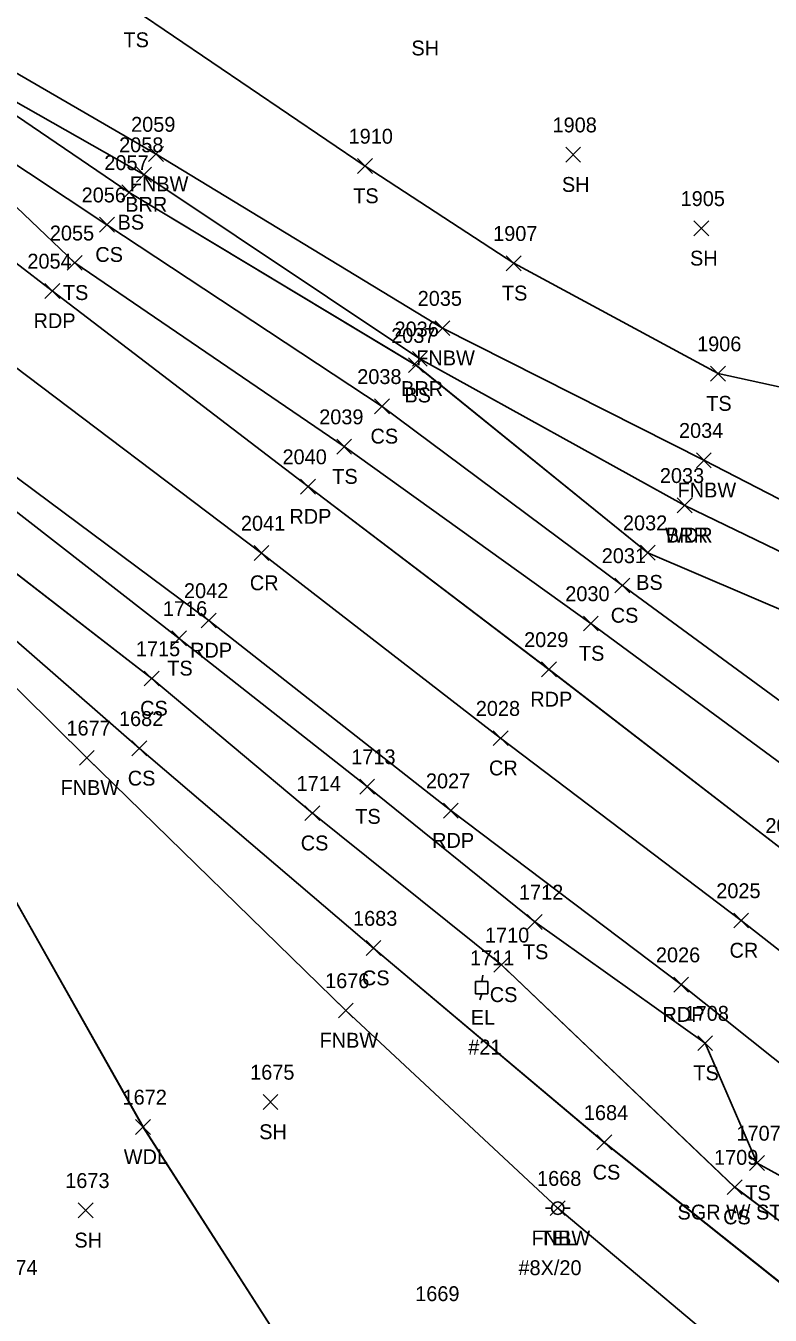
# Model space of a CAD drawing. Extents: x 1415642 to 1422021, y 544543 to 547232.
# Drawn here: x 1415866.3 to 1415966.4, y 546920.1 to 547093.4 of the extents above; entities that cross this region are included whole.
import ezdxf

# ---------------------------------------------------------------- set-up
doc = ezdxf.new("R2010")
doc.units = 0
for name, color, linetype in [('L_A', 7, 'Continuous'), ('L_C', 7, 'Continuous'), ('L_I', 7, 'Continuous'), ('L_TIC', 7, 'Continuous'), ('LABL', 7, 'Continuous'), ('LAWA', 7, 'Continuous'), ('LELB', 7, 'Continuous'), ('LFNC', 7, 'Continuous'), ('P_A', 7, 'Continuous'), ('P_I', 7, 'Continuous'), ('P_TIC', 7, 'Continuous'), ('PET', 7, 'Continuous'), ('PRC', 7, 'Continuous'), ('R_C', 7, 'Continuous'), ('U_A', 7, 'Continuous'), ('U_C', 7, 'Continuous'), ('U_I', 7, 'Continuous'), ('UEPT', 7, 'Continuous'), ('UP', 7, 'Continuous')]:
    doc.layers.add(name, color=color, linetype=linetype)

msp = doc.modelspace()

# ---------------------------------------------------------------- linework, layer by layer
at = {"layer": 'L_TIC'}
for points in [[(1415882.85, 547075.17), (1415884.85, 547077.17)], [(1415884.85, 547075.17), (1415882.85, 547077.17)], [(1415938.9, 547075.09), (1415940.9, 547077.09)], [(1415940.9, 547075.09), (1415938.9, 547077.09)], [(1415881.22, 547072.42), (1415883.22, 547074.42)], [(1415883.22, 547072.42), (1415881.22, 547074.42)], [(1415910.93, 547073.57), (1415912.93, 547075.57)], [(1415912.93, 547073.57), (1415910.93, 547075.57)], [(1415879.24, 547070.02), (1415881.24, 547072.02)], [(1415881.24, 547070.02), (1415879.24, 547072.02)], [(1415876.25, 547065.68), (1415878.25, 547067.68)], [(1415878.25, 547065.68), (1415876.25, 547067.68)], [(1415956.1, 547065.19), (1415958.1, 547067.19)], [(1415958.1, 547065.19), (1415956.1, 547067.19)], [(1415871.92, 547060.56), (1415873.92, 547062.56)], [(1415873.92, 547060.56), (1415871.92, 547062.56)], [(1415930.91, 547060.5), (1415932.91, 547062.5)], [(1415932.91, 547060.5), (1415930.91, 547062.5)], [(1415921.34, 547051.78), (1415923.34, 547053.78)], [(1415923.34, 547051.78), (1415921.34, 547053.78)], [(1415917.77, 547046.8), (1415919.77, 547048.8)], [(1415919.77, 547046.8), (1415917.77, 547048.8)], [(1415918.29, 547047.66), (1415920.29, 547049.66)], [(1415920.29, 547047.66), (1415918.29, 547049.66)], [(1415958.36, 547045.67), (1415960.36, 547047.67)], [(1415960.36, 547045.67), (1415958.36, 547047.67)], [(1415913.22, 547041.27), (1415915.22, 547043.27)], [(1415915.22, 547041.27), (1415913.22, 547043.27)], [(1415908.12, 547035.86), (1415910.12, 547037.86)], [(1415910.12, 547035.86), (1415908.12, 547037.86)], [(1415956.45, 547034.03), (1415958.45, 547036.03)], [(1415958.45, 547034.03), (1415956.45, 547036.03)], [(1415953.88, 547027.97), (1415955.88, 547029.97)], [(1415955.88, 547027.97), (1415953.88, 547029.97)], [(1415953.88, 547027.97), (1415955.88, 547029.97)], [(1415955.88, 547027.97), (1415953.88, 547029.97)], [(1415948.92, 547021.61), (1415950.92, 547023.61)], [(1415950.92, 547021.61), (1415948.92, 547023.61)], [(1415945.5, 547017.2), (1415947.5, 547019.2)], [(1415947.5, 547017.2), (1415945.5, 547019.2)], [(1415941.26, 547012.09), (1415943.26, 547014.09)], [(1415943.26, 547012.09), (1415941.26, 547014.09)], [(1415885.95, 547010.09), (1415887.95, 547012.09)], [(1415887.95, 547010.09), (1415885.95, 547012.09)], [(1415882.27, 547004.7), (1415884.27, 547006.7)], [(1415884.27, 547004.7), (1415882.27, 547006.7)], [(1415880.61, 546995.31), (1415882.61, 546997.31)], [(1415882.61, 546995.31), (1415880.61, 546997.31)], [(1415880.61, 546995.31), (1415882.61, 546997.31)], [(1415882.61, 546995.31), (1415880.61, 546997.31)], [(1415873.55, 546994.04), (1415875.55, 546996.04)], [(1415875.55, 546994.04), (1415873.55, 546996.04)], [(1415911.21, 546990.17), (1415913.21, 546992.17)], [(1415913.21, 546990.17), (1415911.21, 546992.17)], [(1415903.85, 546986.6), (1415905.85, 546988.6)], [(1415905.85, 546986.6), (1415903.85, 546988.6)], [(1415933.73, 546971.98), (1415935.73, 546973.98)], [(1415935.73, 546971.98), (1415933.73, 546973.98)], [(1415912.06, 546968.47), (1415914.06, 546970.47)], [(1415914.06, 546968.47), (1415912.06, 546970.47)], [(1415929.25, 546966.22), (1415931.25, 546968.22)], [(1415931.25, 546966.22), (1415929.25, 546968.22)], [(1415908.35, 546960.09), (1415910.35, 546962.09)], [(1415910.35, 546960.09), (1415908.35, 546962.09)], [(1415956.63, 546955.7), (1415958.63, 546957.7)], [(1415958.63, 546955.7), (1415956.63, 546957.7)], [(1415898.23, 546947.79), (1415900.23, 546949.79)], [(1415900.23, 546947.79), (1415898.23, 546949.79)], [(1415881.09, 546944.44), (1415883.09, 546946.44)], [(1415883.09, 546944.44), (1415881.09, 546946.44)], [(1415943.07, 546942.36), (1415945.07, 546944.36)], [(1415945.07, 546942.36), (1415943.07, 546944.36)], [(1415963.6, 546939.59), (1415965.6, 546941.59)], [(1415965.6, 546939.59), (1415963.6, 546941.59)], [(1415960.59, 546936.35), (1415962.59, 546938.35)], [(1415962.59, 546936.35), (1415960.59, 546938.35)], [(1415873.39, 546933.23), (1415875.39, 546935.23)], [(1415875.39, 546933.23), (1415873.39, 546935.23)], [(1415936.82, 546933.52), (1415938.82, 546935.52)], [(1415938.82, 546933.52), (1415936.82, 546935.52)]]:
    msp.add_lwpolyline(points, dxfattribs=at)
at = {"layer": 'LABL'}
for points in [[(1415954.88, 547028.96), (1415919.29, 547048.67), (1415882.22, 547073.43), (1415848.8, 547092.4), (1415822.78, 547108.48), (1415823.18, 547113.64)], [(1415954.88, 547028.97), (1415919.29, 547048.66), (1415882.22, 547073.42), (1415848.8, 547092.4), (1415822.78, 547108.48), (1415823.18, 547113.63)]]:
    msp.add_lwpolyline(points, dxfattribs=at)
at = {"layer": 'LAWA'}
for points in [[(1415914.11, 546834.35), (1415931.31, 546850.74), (1415944.85, 546869.92), (1415908.68, 546903.98), (1415882.09, 546945.44), (1415862.73, 546979.72), (1415851.29, 546999.16), (1415831.18, 547012.42), (1415802.21, 547036.19), (1415763.17, 547054.94), (1415718.14, 547089.46), (1415689.93, 547108.01)], [(1415914.12, 546834.35), (1415931.31, 546850.75), (1415944.86, 546869.92), (1415908.68, 546903.98), (1415882.1, 546945.44), (1415862.73, 546979.72), (1415851.29, 546999.15), (1415831.18, 547012.42), (1415802.2, 547036.19), (1415763.17, 547054.94), (1415718.15, 547089.45), (1415689.93, 547108.01)], [(1416240.56, 546960.73), (1416233.2, 546953.27), (1416224.51, 546941.93), (1416214.85, 546929.39), (1416199.95, 546923.14), (1416193.46, 546920.24), (1416179.13, 546920.7), (1416159.93, 546927.15), (1416126.32, 546945.38), (1416100.02, 546952.8), (1416028.43, 546991.66), (1415993.05, 547010.51), (1415954.88, 547028.97)], [(1416240.56, 546960.73), (1416233.2, 546953.27), (1416224.51, 546941.93), (1416214.86, 546929.39), (1416199.95, 546923.14), (1416193.46, 546920.24), (1416179.13, 546920.7), (1416159.93, 546927.15), (1416126.32, 546945.39), (1416100.02, 546952.81), (1416028.43, 546991.66), (1415993.05, 547010.51), (1415954.88, 547028.96)]]:
    msp.add_lwpolyline(points, dxfattribs=at)
at = {"layer": 'LELB'}
for points in [[(1416091.47, 546896.23), (1416067.28, 546915.33), (1416036.7, 546941.48), (1416008.25, 546963.65), (1415975.6, 546988.56), (1415942.26, 547013.09), (1415909.12, 547036.86), (1415872.92, 547061.56), (1415845.5, 547087.74), (1415809.03, 547112.5), (1415805.73, 547114.89), (1415787.7, 547125.97), (1415788.24, 547129.84), (1415790.68, 547131.85)], [(1416091.47, 546896.23), (1416067.28, 546915.33), (1416036.71, 546941.48), (1416008.26, 546963.65), (1415975.6, 546988.56), (1415942.26, 547013.09), (1415909.12, 547036.86), (1415872.92, 547061.56), (1415845.5, 547087.74), (1415809.04, 547112.5), (1415805.73, 547114.9), (1415787.7, 547125.97), (1415788.24, 547129.84), (1415790.68, 547131.85)], [(1416157.94, 546955.38), (1416155.92, 546957.27), (1416135.55, 546960.79), (1416132.49, 546973.78), (1416110.9, 546979.13), (1416081.52, 546992.2), (1416051.18, 547012.47), (1416023.77, 547025.27), (1415981.89, 547041.76), (1415959.36, 547046.67), (1415931.91, 547061.5), (1415911.94, 547074.57), (1415881.06, 547095.53), (1415867.9, 547121.94)], [(1416157.94, 546955.38), (1416155.92, 546957.27), (1416135.55, 546960.79), (1416132.49, 546973.77), (1416110.9, 546979.12), (1416081.52, 546992.2), (1416051.18, 547012.47), (1416023.76, 547025.27), (1415981.89, 547041.76), (1415959.36, 547046.67), (1415931.91, 547061.5), (1415911.93, 547074.57), (1415881.06, 547095.53), (1415867.9, 547121.93)], [(1415979.27, 546932.57), (1415964.6, 546940.59), (1415957.63, 546956.7), (1415934.73, 546972.98), (1415912.21, 546991.17), (1415886.95, 547011.09), (1415854.08, 547036.67), (1415824.18, 547059.44), (1415786.82, 547087.62), (1415741.01, 547120.53)], [(1415979.28, 546932.57), (1415964.61, 546940.59), (1415957.63, 546956.7), (1415934.74, 546972.98), (1415912.22, 546991.17), (1415886.96, 547011.09), (1415854.08, 547036.67), (1415824.19, 547059.44), (1415786.82, 547087.62), (1415741.01, 547120.53)], [(1416166.26, 546865.71), (1416159.51, 546874.18), (1416128.86, 546893.05), (1416099.94, 546911.95), (1416080.11, 546927.17), (1416051.61, 546951.27), (1416024.79, 546978.54), (1415989.85, 547005.5), (1415949.92, 547022.61), (1415918.77, 547047.8), (1415880.24, 547071.02), (1415848.8, 547092.4)], [(1416166.26, 546865.71), (1416159.51, 546874.18), (1416128.86, 546893.05), (1416099.95, 546911.94), (1416080.11, 546927.17), (1416051.61, 546951.27), (1416024.79, 546978.54), (1415989.85, 547005.5), (1415949.92, 547022.61), (1415918.78, 547047.8), (1415880.25, 547071.01), (1415848.8, 547092.4)], [(1416210.45, 546810.14), (1416187.24, 546828.5), (1416172.35, 546839.03), (1416162.91, 546845.64), (1416145.69, 546861.76), (1416125.16, 546875.54), (1416093.4, 546901.43), (1416075.19, 546919.9), (1416045.66, 546942.32), (1416039.77, 546946.29), (1416015.88, 546971.97), (1415979.91, 546993.7), (1415946.5, 547018.2), (1415914.22, 547042.27), (1415877.25, 547066.68), (1415845.5, 547087.74)], [(1416210.45, 546810.14), (1416187.24, 546828.5), (1416172.36, 546839.03), (1416162.91, 546845.64), (1416145.7, 546861.76), (1416125.16, 546875.54), (1416093.4, 546901.44), (1416075.18, 546919.9), (1416045.66, 546942.32), (1416039.77, 546946.29), (1416015.88, 546971.97), (1415979.91, 546993.7), (1415946.51, 547018.2), (1415914.22, 547042.27), (1415877.24, 547066.68), (1415845.5, 547087.74)], [(1416200.69, 546756.25), (1416177.76, 546767.63), (1416166.72, 546775.57), (1416158.94, 546780.74), (1416149.8, 546790.95), (1416145.27, 546792.19), (1416135.47, 546803.24), (1416119.09, 546819.38), (1416087.86, 546845.73), (1416058.66, 546867.92), (1416017.63, 546898.15), (1415975.94, 546926.54), (1415961.59, 546937.35), (1415930.25, 546967.22), (1415904.85, 546987.6), (1415883.27, 547005.7), (1415850.56, 547030.99), (1415821.69, 547055.02)], [(1416200.69, 546756.25), (1416177.77, 546767.63), (1416166.72, 546775.57), (1416158.93, 546780.74), (1416149.8, 546790.95), (1416145.28, 546792.19), (1416135.47, 546803.24), (1416119.09, 546819.38), (1416087.87, 546845.73), (1416058.67, 546867.92), (1416017.63, 546898.16), (1415975.95, 546926.55), (1415961.6, 546937.34), (1415930.25, 546967.22), (1415904.86, 546987.6), (1415883.28, 547005.7), (1415850.57, 547030.99), (1415821.7, 547055.02)], [(1415881.61, 546996.31), (1415848.06, 547025.54), (1415815.91, 547049.29)], [(1415881.62, 546996.31), (1415848.06, 547025.54), (1415815.91, 547049.29)], [(1415881.61, 546996.31), (1415913.06, 546969.47), (1415944.07, 546943.36), (1415978.11, 546916.22), (1416009.92, 546888.85), (1416034.36, 546866.02), (1416055.92, 546848.02), (1416074.4, 546832.78), (1416094.73, 546817.39), (1416113.97, 546812.22), (1416083.13, 546840.22), (1416056.24, 546861.43), (1416014.25, 546894.44), (1415975.94, 546926.54)], [(1415881.62, 546996.31), (1415913.07, 546969.47), (1415944.08, 546943.36), (1415978.12, 546916.23), (1416009.93, 546888.84), (1416034.36, 546866.03), (1416055.93, 546848.02), (1416074.4, 546832.78), (1416094.74, 546817.39), (1416113.98, 546812.22), (1416083.14, 546840.22), (1416056.24, 546861.43), (1416014.25, 546894.43), (1415975.95, 546926.55)]]:
    msp.add_lwpolyline(points, dxfattribs=at)
at = {"layer": 'LFNC'}
for points in [[(1416067.58, 546984.06), (1416031.2, 546999.34), (1415996.11, 547015.1), (1415957.45, 547035.03), (1415922.34, 547052.78), (1415883.85, 547076.17), (1415852.09, 547094.57), (1415823.18, 547113.63), (1415819.4, 547116.14), (1415815.46, 547118.48), (1415790.83, 547135.32)], [(1416067.58, 546984.06), (1416031.2, 546999.34), (1415996.12, 547015.09), (1415957.45, 547035.03), (1415922.34, 547052.78), (1415883.85, 547076.17), (1415852.09, 547094.57), (1415823.18, 547113.64), (1415819.41, 547116.14), (1415815.45, 547118.48), (1415790.83, 547135.32)], [(1415844.05, 547025.19), (1415874.55, 546995.04)], [(1415844.05, 547025.19), (1415874.56, 546995.04)], [(1416115.75, 546796.75), (1416105.56, 546801.9), (1416090.13, 546811.78), (1416082.81, 546817.76), (1416078.29, 546817.48), (1416069.09, 546824.45), (1416051.15, 546839.14), (1416026.27, 546859.13), (1416002.28, 546878.71), (1415967.43, 546909.62), (1415937.82, 546934.52), (1415909.35, 546961.09), (1415874.55, 546995.04)], [(1416115.75, 546796.75), (1416105.57, 546801.9), (1416090.14, 546811.78), (1416082.82, 546817.76), (1416078.29, 546817.48), (1416069.1, 546824.45), (1416051.16, 546839.14), (1416026.28, 546859.13), (1416002.28, 546878.71), (1415967.43, 546909.62), (1415937.83, 546934.51), (1415909.36, 546961.09), (1415874.56, 546995.04)]]:
    msp.add_lwpolyline(points, dxfattribs=at)
at = {"layer": 'P_TIC'}
for points in [[(1415868.9, 547056.78), (1415870.9, 547058.78)], [(1415870.9, 547056.78), (1415868.9, 547058.78)], [(1415903.27, 547030.49), (1415905.27, 547032.49)], [(1415905.27, 547030.49), (1415903.27, 547032.49)], [(1415897.02, 547021.56), (1415899.02, 547023.56)], [(1415899.02, 547021.56), (1415897.02, 547023.56)], [(1415889.93, 547012.5), (1415891.93, 547014.5)], [(1415891.93, 547012.5), (1415889.93, 547014.5)], [(1415935.64, 547005.92), (1415937.64, 547007.92)], [(1415937.64, 547005.92), (1415935.64, 547007.92)], [(1415929.15, 546996.68), (1415931.15, 546998.68)], [(1415931.15, 546996.68), (1415929.15, 546998.68)], [(1415922.45, 546986.94), (1415924.45, 546988.94)], [(1415924.45, 546986.94), (1415922.45, 546988.94)], [(1415961.46, 546972.18), (1415963.46, 546974.18)], [(1415963.46, 546972.18), (1415961.46, 546974.18)], [(1415953.4, 546963.56), (1415955.4, 546965.56)], [(1415955.4, 546963.56), (1415953.4, 546965.56)]]:
    msp.add_lwpolyline(points, dxfattribs=at)
at = {"layer": 'PET'}
for points in [[(1415969.06, 546981.93), (1415936.64, 547006.92), (1415904.27, 547031.49), (1415869.9, 547057.78), (1415840.56, 547080.38), (1415803.16, 547107.61), (1415784.15, 547121.85), (1415763.35, 547137.62), (1415738.26, 547155), (1415710.8, 547176.64), (1415691.9, 547191.05)], [(1415969.07, 546981.93), (1415936.65, 547006.92), (1415904.27, 547031.49), (1415869.9, 547057.78), (1415840.56, 547080.38), (1415803.16, 547107.61), (1415784.15, 547121.85), (1415763.35, 547137.62), (1415738.26, 547155), (1415710.8, 547176.64), (1415691.9, 547191.04)], [(1415982.21, 546942.39), (1415954.4, 546964.56), (1415923.45, 546987.94), (1415890.93, 547013.5), (1415855.69, 547039.7), (1415826.51, 547062.15), (1415788.27, 547090.37), (1415749.29, 547120.02), (1415723.83, 547138.72), (1415697.43, 547158.88), (1415677.46, 547174.08)], [(1415982.21, 546942.39), (1415954.4, 546964.56), (1415923.45, 546987.94), (1415890.93, 547013.5), (1415855.69, 547039.7), (1415826.51, 547062.15), (1415788.27, 547090.37), (1415749.28, 547120.03), (1415723.83, 547138.72), (1415697.43, 547158.88), (1415677.46, 547174.08)]]:
    msp.add_lwpolyline(points, dxfattribs=at)
at = {"layer": 'PRC'}
for points in [[(1415989.92, 546951.68), (1415962.46, 546973.18), (1415930.15, 546997.68), (1415898.02, 547022.56), (1415862.93, 547049.07), (1415833.82, 547071.85), (1415795.61, 547099.36), (1415756.73, 547129.15), (1415731.28, 547147.85), (1415704.22, 547168.12), (1415684.99, 547182.73)], [(1415989.92, 546951.67), (1415962.46, 546973.18), (1415930.15, 546997.68), (1415898.02, 547022.56), (1415862.93, 547049.07), (1415833.81, 547071.85), (1415795.61, 547099.36), (1415756.73, 547129.15), (1415731.28, 547147.85), (1415704.22, 547168.13), (1415684.99, 547182.72)]]:
    msp.add_lwpolyline(points, dxfattribs=at)
at = {"layer": 'UEPT'}
for p, q in [((1415927.76, 546965.83), (1415927.6, 546965)), ((1415926.76, 546963.33), (1415926.76, 546965)), ((1415926.76, 546965), (1415928.43, 546965)), ((1415928.43, 546963.33), (1415926.76, 546963.33)), ((1415927.35, 546962.5), (1415927.6, 546963.33)), ((1415927.6, 546964.17), (1415927.6, 546964.17)), ((1415928.43, 546965), (1415928.43, 546963.33))]:
    msp.add_line(p, q, dxfattribs=at)
at = {"layer": 'UP'}
for p, q in [((1415936.16, 546934.51), (1415936.99, 546934.51)), ((1415937.82, 546934.52), (1415937.82, 546934.52)), ((1415939.49, 546934.52), (1415938.66, 546934.52)), ((1415938.66, 546934.52), (1415938.66, 546934.52)), ((1415939.49, 546934.52), (1415939.49, 546934.52))]:
    msp.add_line(p, q, dxfattribs=at)
msp.add_circle((1415937.82, 546934.52), 0.833, dxfattribs=at)

# ---------------------------------------------------------------- texts
at = {"layer": 'L_A'}
for s, p in [('TS', (1415879.47, 547090.53)), ('SH', (1415918.16, 547089.43)), ('FNBW', (1415880.32, 547071.17)), ('SH', (1415938.38, 547071.09)), ('TS', (1415910.34, 547069.57)), ('BRR', (1415879.71, 547068.42)), ('BS', (1415878.68, 547066.02)), ('CS', (1415875.69, 547061.68)), ('SH', (1415955.59, 547061.19)), ('TS', (1415871.33, 547056.56)), ('TS', (1415930.32, 547056.5)), ('FNBW', (1415918.81, 547047.78)), ('BRR', (1415916.78, 547043.66)), ('BS', (1415917.22, 547042.8)), ('TS', (1415957.77, 547041.67)), ('CS', (1415912.66, 547037.27)), ('TS', (1415907.53, 547031.86)), ('FNBW', (1415953.92, 547030.03)), ('WDR', (1415952.24, 547023.97)), ('BRR', (1415952.36, 547023.97)), ('BS', (1415948.36, 547017.61)), ('CS', (1415944.94, 547013.2)), ('TS', (1415940.67, 547008.09)), ('TS', (1415885.36, 547006.09)), ('CS', (1415881.71, 547000.7)), ('CS', (1415880.05, 546991.31)), ('CS', (1415880.05, 546991.31)), ('FNBW', (1415871.02, 546990.04)), ('TS', (1415910.62, 546986.17)), ('CS', (1415903.29, 546982.6)), ('TS', (1415933.14, 546967.98)), ('CS', (1415911.51, 546964.47)), ('CS', (1415928.69, 546962.22)), ('FNBW', (1415905.82, 546956.09)), ('TS', (1415956.04, 546951.7)), ('SH', (1415897.71, 546943.79)), ('WDL', (1415879.51, 546940.44)), ('CS', (1415942.51, 546938.36)), ('TS', (1415963.01, 546935.59)), ('CS', (1415960.04, 546932.35)), ('SH', (1415872.88, 546929.23)), ('FNBW', (1415934.3, 546929.52))]:
    msp.add_text(s, height=2, dxfattribs=at).set_placement(p)
at = {"layer": 'L_C'}
msp.add_text('#8X/20', height=2, dxfattribs=at).set_placement((1415932.54, 546925.52))
at = {"layer": 'L_I'}
for s, p in [('2059', (1415880.5, 547079.17)), ('1908', (1415937.12, 547079.09)), ('1910', (1415909.72, 547077.57)), ('2058', (1415878.89, 547076.42)), ('2057', (1415876.9, 547074.02)), ('2056', (1415873.85, 547069.68)), ('1905', (1415954.33, 547069.19)), ('2055', (1415869.58, 547064.56)), ('1907', (1415929.14, 547064.5)), ('2035', (1415919, 547055.78)), ('2036', (1415915.89, 547051.66)), ('2037', (1415915.44, 547050.8)), ('1906', (1415956.54, 547049.67)), ('2038', (1415910.88, 547045.27)), ('2039', (1415905.77, 547039.86)), ('2034', (1415954.11, 547038.03)), ('2033', (1415951.54, 547031.97)), ('2033', (1415951.54, 547031.97)), ('2032', (1415946.58, 547025.61)), ('2031', (1415943.73, 547021.2)), ('2030', (1415938.83, 547016.09)), ('1716', (1415884.77, 547014.09)), ('1715', (1415881.14, 547008.7)), ('1677', (1415871.81, 546998.04)), ('1682', (1415878.87, 546999.31)), ('1682', (1415878.87, 546999.31)), ('1713', (1415910.08, 546994.17)), ('1714', (1415902.73, 546990.6)), ('1712', (1415932.61, 546975.98)), ('1683', (1415910.32, 546972.47)), ('1710', (1415928.04, 546970.22)), ('1676', (1415906.56, 546964.09)), ('1708', (1415954.86, 546959.7)), ('1675', (1415896.49, 546951.79)), ('1672', (1415879.35, 546948.44)), ('1684', (1415941.33, 546946.36)), ('1707', (1415961.83, 546943.59)), ('1709', (1415958.82, 546940.35)), ('1673', (1415871.65, 546937.23)), ('1668', (1415935.04, 546937.52)), ('1674', (1415861.98, 546925.55)), ('1669', (1415918.67, 546922.03))]:
    msp.add_text(s, height=2, dxfattribs=at).set_placement(p)
at = {"layer": 'P_A'}
for s, p in [('RDP', (1415867.39, 547052.78)), ('RDP', (1415901.76, 547026.49)), ('CR', (1415896.45, 547017.56)), ('RDP', (1415888.42, 547008.5)), ('RDP', (1415934.13, 547001.92)), ('CR', (1415928.58, 546992.68)), ('RDP', (1415920.94, 546982.94)), ('CR', (1415960.9, 546968.18)), ('RDP', (1415951.89, 546959.56))]:
    msp.add_text(s, height=2, dxfattribs=at).set_placement(p)
at = {"layer": 'P_I'}
for s, p in [('2054', (1415866.56, 547060.78)), ('2040', (1415900.84, 547034.49)), ('2041', (1415895.25, 547025.56)), ('2042', (1415887.6, 547016.5)), ('2029', (1415933.3, 547009.92)), ('2028', (1415926.81, 547000.68)), ('2027', (1415920.11, 546990.94)), ('2024', (1415965.72, 546984.93)), ('2025', (1415959.12, 546976.18)), ('2026', (1415951.01, 546967.56))]:
    msp.add_text(s, height=2, dxfattribs=at).set_placement(p)
at = {"layer": 'R_C'}
msp.add_text('SGR W/ STEEL POST', height=2, dxfattribs=at).set_placement((1415953.91, 546932.99))
at = {"layer": 'U_A'}
for s, p in [('EL', (1415926.13, 546959.17)), ('TEL', (1415935.38, 546929.52))]:
    msp.add_text(s, height=2, dxfattribs=at).set_placement(p)
at = {"layer": 'U_C'}
msp.add_text('#21', height=2, dxfattribs=at).set_placement((1415925.8, 546955.17))
at = {"layer": 'U_I'}
for s, p in [('1711', (1415926.04, 546967.17)), ('1668', (1415935.04, 546937.52))]:
    msp.add_text(s, height=2, dxfattribs=at).set_placement(p)

doc.saveas('drawing.dxf')
